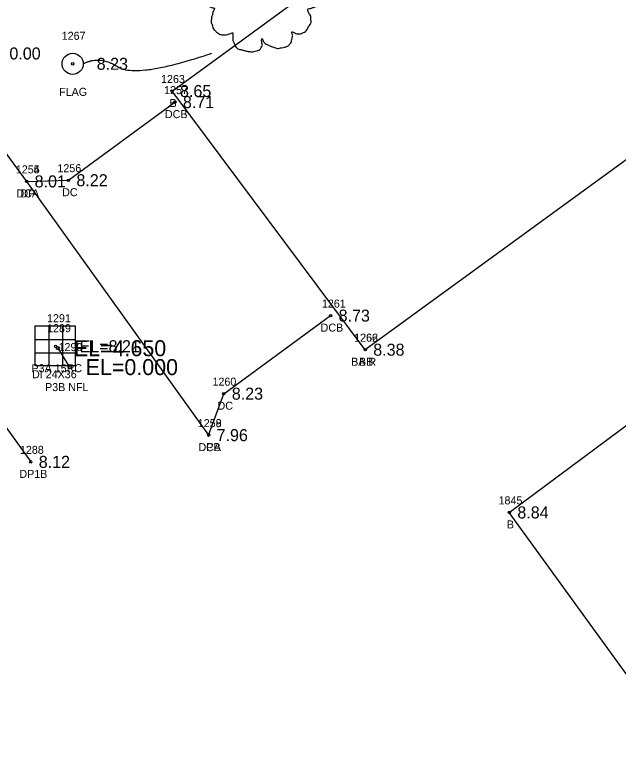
# Model space of a CAD drawing. Extents: x 2608598 to 2610682, y 641451 to 643526.
# Drawn here: x 2608978.5 to 2609053.8, y 642927.9 to 643021 of the extents above; entities that cross this region are included whole.
import ezdxf

# ---------------------------------------------------------------- set-up
doc = ezdxf.new("R2010")
doc.units = 0
for name, color, linetype in [('RD_EX_Bldg', 7, 'Continuous'), ('RD_EX_Bldg_txCode', 7, 'Continuous'), ('RD_EX_BldgApp_txCode', 7, 'Continuous'), ('RD_EX_Conc', 7, 'Continuous'), ('RD_EX_Conc_txCode', 7, 'Continuous'), ('RD_EX_DR_Inlet', 7, 'Continuous'), ('RD_EX_DR_Inlet_txCode', 7, 'Continuous'), ('RD_EX_DR_Pipe', 7, 'Continuous'), ('RD_EX_DR_Pipe_txCode', 7, 'Continuous'), ('RD_EX_Driveway', 7, 'Continuous'), ('RD_EX_Driveway_txCode', 7, 'Continuous'), ('RD_EX_SU_Telecom', 7, 'Continuous'), ('RD_EX_TX_Bldg_ELEV', 7, 'Continuous'), ('RD_EX_TX_BldgApp_ELEV', 7, 'Continuous'), ('RD_EX_TX_Conc_ELEV', 7, 'Continuous'), ('RD_EX_TX_DR_Inlet_ELEV', 7, 'Continuous'), ('RD_EX_TX_Driveway_ELEV', 7, 'Continuous'), ('RD_EX_TX_DV_Prop_ELEV', 7, 'Continuous'), ('RD_EX_VEG', 7, 'Continuous'), ('RD_SMD_Locator', 7, 'Continuous'), ('RD_TX_Pipe_ElevEX', 7, 'Continuous')]:
    doc.layers.add(name, color=color, linetype=linetype)

msp = doc.modelspace()

# ---------------------------------------------------------------- linework, layer by layer
at = {"layer": 'RD_EX_Bldg'}
for points in [[(2609022.28, 642979.2), (2608998.158, 643011.514), (2609058.633, 643055.656), (2609082.824, 643023.33), (2609022.28, 642979.2)], [(2609106.373, 643008.038), (2609128.796, 642977.102), (2609062.694, 642927.938), (2609040.271, 642958.874), (2609106.373, 643008.038)]]:
    msp.add_lwpolyline(points, dxfattribs=at)
at = {"layer": 'RD_EX_Conc'}
for points in [[(2608980.009, 643000.224), (2608985.222, 643000.374), (2608998.52, 643010.125)], [(2609002.723, 642968.528), (2609004.622, 642973.708), (2609017.96, 642983.46)]]:
    msp.add_lwpolyline(points, dxfattribs=at)
at = {"layer": 'RD_EX_DR_Inlet'}
for p, q in [((2608982.78, 642982.193), (2608982.78, 642977.193)), ((2608984.48, 642982.193), (2608984.48, 642977.193)), ((2608981.08, 642980.493), (2608986.08, 642980.493)), ((2608981.08, 642978.793), (2608986.08, 642978.793))]:
    msp.add_line(p, q, dxfattribs=at)
msp.add_lwpolyline([(2608981.08, 642977.193), (2608981.08, 642982.193), (2608986.08, 642982.193), (2608986.08, 642977.193)], close=True, dxfattribs=at)
at = {"layer": 'RD_EX_DR_Pipe'}
msp.add_line((2608983.907, 642979.39), (2608985.381, 642977.03), dxfattribs=at)
at = {"layer": 'RD_EX_Driveway'}
for points in [[(2608966.974, 643044.203), (2608964.832, 643033.445), (2608965.027, 643024.995), (2608967.043, 643017.848), (2608980.009, 643000.224), (2609002.723, 642968.528)], [(2608926.378, 643013.48), (2608937.792, 643013.459), (2608947.008, 643010.003), (2608952.733, 643003.787), (2608980.52, 642965.191)]]:
    msp.add_lwpolyline(points, dxfattribs=at)
at = {"layer": 'RD_EX_SU_Telecom'}
msp.add_circle((2608985.757, 643014.911), 1.32, dxfattribs=at)
msp.add_open_spline([(2608987.077, 643014.911), (2608989.081, 643016.01), (2608993.763, 643013.06), (2609003.128, 643016.241)], degree=2, dxfattribs=at)
at = {"layer": 'RD_EX_VEG'}
for points in [[(2609009.011, 643030.988), (2609008.711, 643031.013), (2609008.387, 643030.913), (2609008.137, 643030.813), (2609007.912, 643030.738), (2609007.687, 643030.638), (2609007.387, 643030.463), (2609007.162, 643030.263), (2609007.037, 643030.013), (2609006.987, 643029.788), (2609006.937, 643029.513), (2609006.937, 643029.338), (2609006.812, 643029.313), (2609006.662, 643029.338), (2609006.412, 643029.413), (2609006.162, 643029.413), (2609005.913, 643029.413), (2609005.563, 643029.388), (2609005.213, 643029.388), (2609004.938, 643029.338), (2609004.613, 643029.288), (2609004.238, 643029.163), (2609003.888, 643029.038), (2609003.589, 643028.788), (2609003.339, 643028.314), (2609003.214, 643027.964), (2609003.064, 643027.714), (2609003.214, 643027.264), (2609003.389, 643026.914), (2609003.414, 643026.714), (2609003.489, 643026.29), (2609003.589, 643026.065), (2609003.714, 643025.865), (2609003.639, 643025.84), (2609003.264, 643025.79), (2609002.964, 643025.69), (2609002.539, 643025.465), (2609002.314, 643025.24), (2609002.214, 643024.915), (2609002.189, 643024.565), (2609002.089, 643024.365), (2609002.014, 643024.091), (2609001.989, 643024.016), (2609001.939, 643023.691), (2609002.039, 643023.241), (2609002.064, 643022.891), (2609002.189, 643022.666), (2609002.339, 643022.491), (2609002.514, 643022.241), (2609002.914, 643022.016), (2609003.239, 643021.916), (2609003.439, 643021.892), (2609003.264, 643021.392), (2609003.214, 643021.042), (2609003.089, 643020.642), (2609003.089, 643020.567), (2609003.039, 643020.092), (2609003.189, 643019.767), (2609003.264, 643019.393), (2609003.439, 643019.168), (2609003.714, 643018.868), (2609004.038, 643018.643), (2609004.538, 643018.518), (2609004.938, 643018.543), (2609005.513, 643018.718), (2609005.763, 643018.793), (2609005.738, 643018.618), (2609005.763, 643018.243), (2609005.763, 643017.818), (2609005.913, 643017.493), (2609006.013, 643017.219), (2609006.162, 643016.969), (2609006.487, 643016.744), (2609006.887, 643016.669), (2609007.312, 643016.519), (2609007.762, 643016.444), (2609008.262, 643016.419), (2609008.861, 643016.569), (2609009.136, 643016.694), (2609009.236, 643016.869), (2609009.436, 643017.244), (2609009.386, 643017.468), (2609009.411, 643018.068), (2609009.511, 643017.893), (2609009.686, 643017.543), (2609010.186, 643017.244), (2609010.586, 643017.069), (2609011.06, 643016.919), (2609011.36, 643016.844), (2609011.835, 643016.919), (2609012.21, 643016.994), (2609012.585, 643017.119), (2609012.885, 643017.393), (2609013.059, 643017.668), (2609013.109, 643017.943), (2609013.184, 643018.318), (2609013.234, 643018.493)], [(2609013.234, 643018.493), (2609013.159, 643018.668), (2609013.109, 643018.918), (2609013.184, 643018.893), (2609013.359, 643018.843), (2609013.634, 643018.718), (2609013.859, 643018.643), (2609014.184, 643018.668), (2609014.459, 643018.768), (2609014.909, 643019.043), (2609015.184, 643019.518), (2609015.458, 643019.917), (2609015.533, 643020.242), (2609015.483, 643020.467), (2609015.458, 643020.967), (2609015.258, 643021.217), (2609015.208, 643021.342), (2609015.109, 643021.742), (2609015.184, 643021.792), (2609015.458, 643021.842), (2609015.833, 643021.966), (2609016.108, 643022.091), (2609016.333, 643022.266), (2609016.408, 643022.491), (2609016.383, 643022.891), (2609016.433, 643023.291), (2609016.358, 643023.441), (2609016.258, 643023.591), (2609016.183, 643023.791), (2609016.033, 643023.941), (2609015.933, 643024.091), (2609015.833, 643024.19), (2609015.708, 643024.34), (2609015.533, 643024.465), (2609015.383, 643024.515), (2609015.333, 643024.665), (2609015.483, 643024.865), (2609015.533, 643024.965), (2609015.558, 643025.19), (2609015.783, 643025.54), (2609015.833, 643025.94), (2609015.783, 643026.365), (2609015.733, 643026.639), (2609015.583, 643026.914), (2609015.383, 643027.164), (2609015.258, 643027.339), (2609015.084, 643027.464), (2609014.759, 643027.589), (2609014.509, 643027.639), (2609014.159, 643027.639), (2609013.959, 643027.689), (2609013.984, 643027.739), (2609013.984, 643027.889), (2609013.984, 643028.164), (2609013.909, 643028.614), (2609013.759, 643029.113), (2609013.759, 643029.138), (2609013.659, 643029.388), (2609013.434, 643029.588), (2609013.259, 643029.688), (2609013.059, 643029.813), (2609012.81, 643029.838), (2609012.51, 643029.838), (2609012.235, 643029.788), (2609012.035, 643029.688), (2609011.86, 643029.563), (2609011.785, 643029.713), (2609011.685, 643030.013), (2609011.635, 643030.163), (2609011.485, 643030.338), (2609011.26, 643030.538), (2609010.81, 643030.663), (2609010.186, 643030.588), (2609009.886, 643030.388), (2609009.736, 643030.213), (2609009.686, 643030.338), (2609009.486, 643030.538), (2609009.386, 643030.713), (2609009.211, 643030.838), (2609009.061, 643030.938), (2609008.961, 643030.988)]]:
    msp.add_spline(points, degree=3, dxfattribs=at)
at = {"layer": 'RD_SMD_Locator'}
for centre, radius in [((2608985.757, 643014.911), 0.15), ((2608998.158, 643011.514), 0.15), ((2608998.52, 643010.125), 0.15), ((2608980.009, 643000.224), 0.15), ((2608980.009, 643000.224), 0.15), ((2608985.222, 643000.374), 0.15), ((2609017.96, 642983.46), 0.15), ((2608983.618, 642979.635), 0.15), ((2608983.907, 642979.39), 0.2), ((2609022.28, 642979.2), 0.15), ((2609022.28, 642979.2), 0.15), ((2608985.381, 642977.03), 0.2), ((2609004.622, 642973.708), 0.15), ((2609002.723, 642968.528), 0.15), ((2609002.723, 642968.528), 0.15), ((2608980.52, 642965.191), 0.15), ((2609040.271, 642958.874), 0.15)]:
    msp.add_circle(centre, radius, dxfattribs=at)

# ---------------------------------------------------------------- texts
at = {"layer": 'RD_EX_Bldg_txCode'}
for s, p in [('1263', (2608996.788, 643012.514)), ('B', (2608997.851, 643009.514)), ('1266', (2609020.886, 642980.2)), ('1262', (2609020.91, 642980.2)), ('BA R', (2609020.524, 642977.2)), ('BB', (2609021.501, 642977.2)), ('1845', (2609038.924, 642959.874)), ('B', (2609039.964, 642956.874))]:
    msp.add_text(s, height=1, dxfattribs=at).set_placement(p)
at = {"layer": 'RD_EX_BldgApp_txCode'}
for s, p in [('1267', (2608984.387, 643017.911)), ('FLAG', (2608984.064, 643010.911))]:
    msp.add_text(s, height=1, dxfattribs=at).set_placement(p)
at = {"layer": 'RD_EX_Conc_txCode'}
for s, p in [('1257', (2608997.173, 643011.125)), ('DCB', (2608997.268, 643008.125)), ('1255', (2608978.662, 643001.224)), ('1256', (2608983.852, 643001.374)), ('DCA', (2608978.741, 642998.224)), ('DC', (2608984.442, 642998.374)), ('1261', (2609016.873, 642984.46)), ('DCB', (2609016.708, 642981.46)), ('1260', (2609003.212, 642974.708)), ('DC', (2609003.842, 642971.708)), ('1259', (2609001.377, 642969.528)), ('DCA', (2609001.456, 642966.528))]:
    msp.add_text(s, height=1, dxfattribs=at).set_placement(p)
at = {"layer": 'RD_EX_DR_Inlet_txCode'}
for s, p in [('1291', (2608982.555, 642982.635)), ('DI 24X36', (2608980.681, 642975.635))]:
    msp.add_text(s, height=1, dxfattribs=at).set_placement(p)
at = {"layer": 'RD_EX_DR_Pipe_txCode'}
for s, p in [('1289', (2608982.56, 642981.39)), ('1290', (2608983.995, 642979.03)), ('P3A 15RC', (2608980.615, 642976.39)), ('P3B NFL', (2608982.31, 642974.03))]:
    msp.add_text(s, height=1, dxfattribs=at).set_placement(p)
at = {"layer": 'RD_EX_Driveway_txCode'}
for s, p in [('1254', (2608978.662, 643001.224)), ('DP', (2608979.229, 642998.224)), ('1258', (2609001.377, 642969.528)), ('1288', (2608979.173, 642966.191)), ('DPB', (2609001.471, 642966.528)), ('DP1B', (2608979.103, 642963.191))]:
    msp.add_text(s, height=1, dxfattribs=at).set_placement(p)
at = {"layer": 'RD_EX_TX_Bldg_ELEV'}
for s, p in [('8.65', (2608999.158, 643010.764)), ('8.38', (2609023.28, 642978.45)), ('8.38', (2609023.28, 642978.45)), ('8.84', (2609041.271, 642958.124))]:
    msp.add_text(s, height=1.5, dxfattribs=at).set_placement(p)
at = {"layer": 'RD_EX_TX_BldgApp_ELEV'}
msp.add_text('8.23', height=1.5, dxfattribs=at).set_placement((2608988.757, 643014.161))
at = {"layer": 'RD_EX_TX_Conc_ELEV'}
for s, p in [('8.71', (2608999.52, 643009.375)), ('8.01', (2608981.009, 642999.474)), ('8.22', (2608986.222, 642999.624)), ('8.73', (2609018.96, 642982.71)), ('8.23', (2609005.622, 642972.958)), ('7.96', (2609003.723, 642967.778))]:
    msp.add_text(s, height=1.5, dxfattribs=at).set_placement(p)
at = {"layer": 'RD_EX_TX_DR_Inlet_ELEV'}
msp.add_text('EL=8.21', height=1.5, dxfattribs=at).set_placement((2608986.618, 642978.885))
at = {"layer": 'RD_EX_TX_Driveway_ELEV'}
for s, p in [('8.01', (2608981.009, 642999.474)), ('7.96', (2609003.723, 642967.778)), ('8.12', (2608981.52, 642964.441))]:
    msp.add_text(s, height=1.5, dxfattribs=at).set_placement(p)
at = {"layer": 'RD_EX_TX_DV_Prop_ELEV'}
msp.add_text('0.00', height=1.5, dxfattribs=at).set_placement((2608977.856, 643015.458))
at = {"layer": 'RD_TX_Pipe_ElevEX'}
for s, p in [('EL=4.650', (2608985.907, 642978.39)), ('EL=0.000', (2608987.381, 642976.03))]:
    msp.add_text(s, height=2, dxfattribs=at).set_placement(p)

doc.saveas('drawing.dxf')
